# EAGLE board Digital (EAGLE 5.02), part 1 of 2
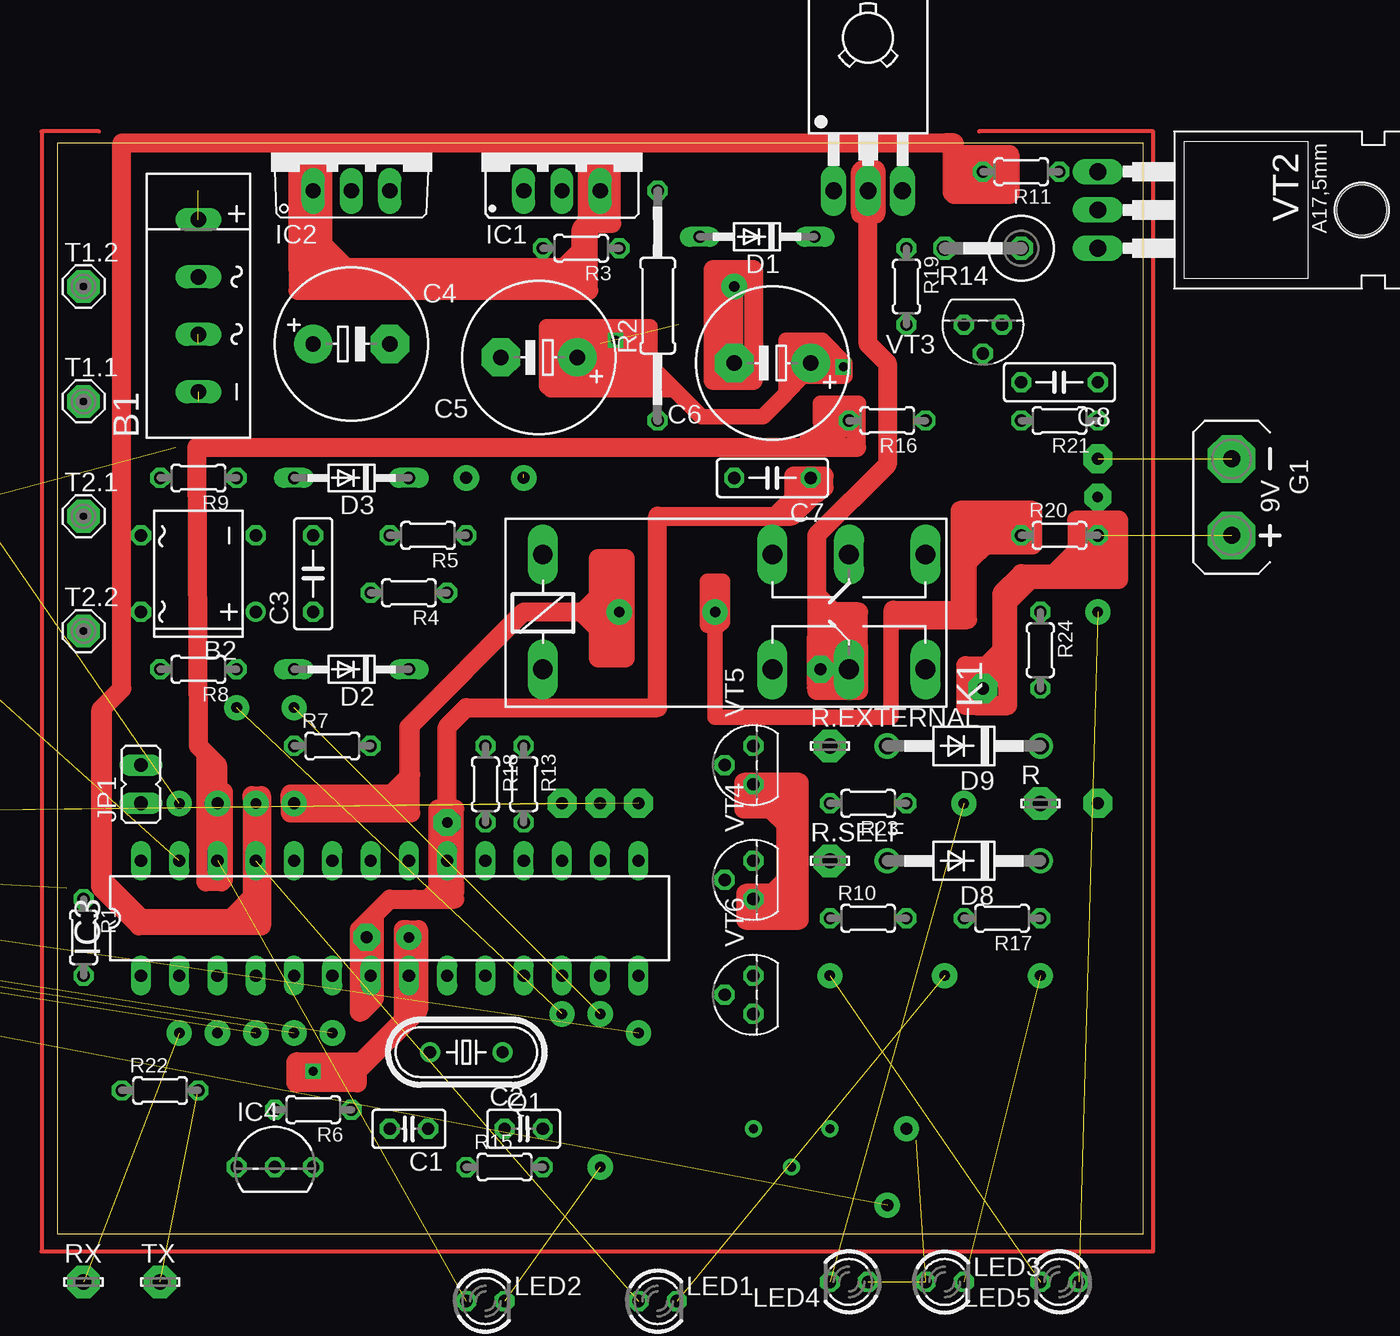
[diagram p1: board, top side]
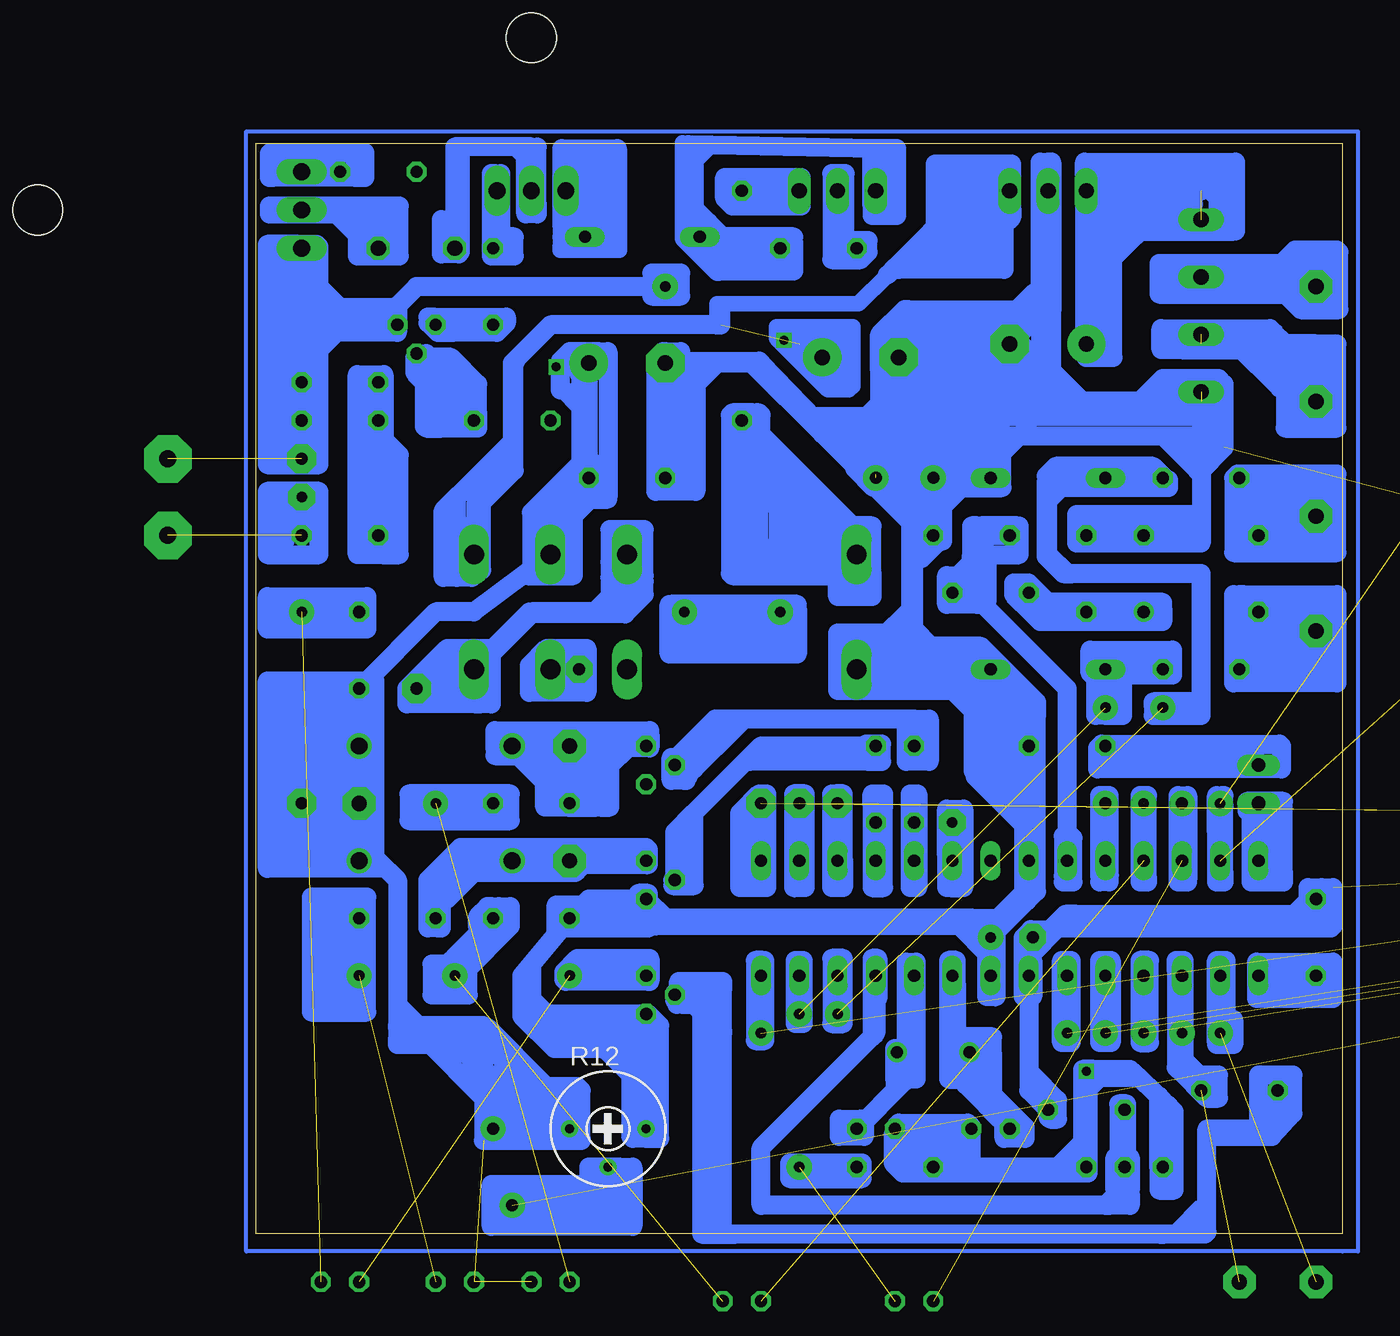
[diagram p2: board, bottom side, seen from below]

Size 72.06 x 72.38 mm. Coordinates in mm from the lower left corner, seen from the top.
Outline: 0,0 72.06,0 72.06,72.38 0,72.38 0,0
Copper layers (1*16): Top 0.035mm / dielectric 1.5mm / Bottom 0.035mm
Design rules "default": minimum track width 10mil, minimum drill 24mil, track to track 8mil, track to pad 8mil, pad to pad 8mil, via to via 8mil, smd to smd 8mil, copper to edge 40mil, drill to drill 8mil, minimum pad ring 10mil, minimum via ring 8mil, stop-mask expansion 4mil, vias tented up to drill 0mil, thermal gap 10mil

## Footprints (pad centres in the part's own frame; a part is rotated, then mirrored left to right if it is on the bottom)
2KBP = drill 1.016 long: + 5.715,0; - -5.715,0; AC1 -1.905,0; AC2 1.905,0
DB = drill 0.813 round: + -2.54,-3.81 | drill 0.813 octagon: - 2.54,-3.81; AC1 2.54,3.81; AC2 -2.54,3.81
C025-025X050 = drill 0.813 octagon: 1 -1.27,0; 2 1.27,0
C050-025X075 = drill 0.813 octagon: 1 -2.54,0; 2 2.54,0
E5-10,5 = drill 1.016 pad 2.54 round: + -2.54,0 | drill 1.016 pad 2.54 octagon: - 2.54,0
DO34-7 = drill 0.813 long: A 3.81,0; C -3.81,0
DO41-10 = drill 1.118 round: A 5.08,0; C -5.08,0
TUXGR_16X2_R2 = drill 1 pad 1.676 round: 1 -32,15.5; 2 -29.46,15.5; 3 -26.92,15.5; 4 -24.38,15.5; 5 -21.84,15.5; 6 -19.3,15.5; 7 -16.76,15.5; 8 -14.22,15.5; 9 -11.68,15.5; 10 -9.14,15.5; 11 -6.6,15.5; 12 -4.06,15.5; 13 -1.52,15.5; 14 1.02,15.5; 15 3.56,15.5; 16 6.1,15.5 | hole 2.5: -37.5,-15.5; 37.5,-15.5; -37.5,15.5; 37.5,15.5
AB9V = drill 1.118 pad 3.15 octagon: + 0,2.54; - 0,-2.54
317TS = drill 1.016 long: 1 -2.54,-2.54; 2 0,-2.54; 3 2.54,-2.54
TO220V = drill 1.016 long: 1 -2.54,-2.54; 2 0,-2.54; 3 2.54,-2.54
DIL28-3 = drill 0.813 long: 1 -16.51,-3.81; 2 -13.97,-3.81; 3 -11.43,-3.81; 4 -8.89,-3.81; 5 -6.35,-3.81; 6 -3.81,-3.81; 7 -1.27,-3.81; 8 1.27,-3.81; 9 3.81,-3.81; 10 6.35,-3.81; 11 8.89,-3.81; 12 11.43,-3.81; 13 13.97,-3.81; 14 16.51,-3.81; 15 16.51,3.81; 16 13.97,3.81; 17 11.43,3.81; 18 8.89,3.81; 19 6.35,3.81; 20 3.81,3.81; 21 1.27,3.81; 22 -1.27,3.81; 23 -3.81,3.81; 24 -6.35,3.81; 25 -8.89,3.81; 26 -11.43,3.81; 27 -13.97,3.81; 28 -16.51,3.81
TO92- = drill 0.813 octagon: 1 -2.54,0; 2 0,0; 3 2.54,0
JP1 = drill 0.914 long: 1 0,-1.27; 2 0,1.27
F4052 = drill 1.321 long: 1 -3.81,3.81; 2 -3.81,-3.81; O1 11.43,-3.81; O2 11.43,3.81; P1 16.51,-3.81; P2 16.51,3.81; S1 21.59,-3.81; S2 21.59,3.81
LED3MM = drill 0.813 octagon: A -1.27,0; K 1.27,0
HC49/S = drill 0.813 round: 1 -2.413,0; 2 2.413,0
LSP10 = drill 1.016 pad 2.159 octagon: MP 0,0
0204/5 = drill 0.813 octagon: 1 -2.54,0; 2 2.54,0
0207/15 = drill 0.813 octagon: 1 -7.62,0; 2 7.62,0
RTRIM3339P = drill 0.61 round: 1 -2.54,0; 2 0,-2.54; 3 2.54,0
0414V = drill 1.016 octagon: 1 -2.54,0; 2 2.54,0
B3F-10XX = drill 1.016 long: 1 -3.251,2.261; 2 3.251,2.261; 3 -3.251,-2.261; 4 3.251,-2.261
MCS10B = drill 1.016 pad 2.159 octagon: MP 0,0
TO126 = drill 1.118 long: 1 -2.286,-5.08; 2 0,-5.08; 3 2.286,-5.08 | hole 3.302: 0,5.08
TO220 = drill 1.118 long: 1 -2.54,-6.35; 2 0,-6.35; 3 2.54,-6.35 | hole 3.302: 0,11.176
TO92 = drill 0.813 octagon: 1 1.27,0; 2 0,1.905; 3 -1.27,0

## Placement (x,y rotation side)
B1  KBP210  [2KBP]  9.36,61.59 90 top
B2  DB107  [DB]  9.36,43.81 90 top
C1  15  [C025-025X050]  23.33,6.98 180 top
C2  15  [C025-025X050]  30.95,6.98 0 top
C3  0.01  [C050-025X075]  16.98,43.81 90 top
C4  470uFx25V  [E5-10,5]  19.52,59.05 0 top
C5  4700u x 16V  [E5-10,5]  31.97,58.16 180 top
C6  [E5-10,5]  47.46,57.78 180 top
C7  0.1u  [C050-025X075]  47.46,50.16 180 top
C8  0.01  [C050-025X075]  66.51,56.51 180 top
D1  1N4004  [DO34-7]  46.44,66.16 180 top
D2  [DO34-7]  19.52,37.46 180 top
D3  [DO34-7]  19.52,50.16 180 top
D4  [DO34-7]  not placed on the board
D5  [DO34-7]  not placed on the board
D6  [DO34-7]  not placed on the board
D7  [DO34-7]  not placed on the board
D8  1N4004  [DO41-10]  60.16,24.76 180 top
D9  1N4004  [DO41-10]  60.16,32.38 180 top
DIS1  [TUXGR_16X2_R2]  not placed on the board
G1  AB5V  [AB9V]  not placed on the board
IC1  LM317  [317TS]  33.49,71.75 0 top
IC2  7805TV  [TO220V]  19.52,71.75 0 top
IC3  MEGA8-P  [DIL28-3]  22.06,20.95 0 top
IC4  DS18B20  [TO92-]  14.44,4.44 0 top
JP1  [JP1]  5.55,29.84 0 top
K1  4052  [F4052]  36.03,41.27 0 top
LED1  [LED3MM]  not placed on the board
LED2  [LED3MM]  not placed on the board
LED3  [LED3MM]  not placed on the board
LED4  [LED3MM]  not placed on the board
LED5  [LED3MM]  not placed on the board
Q1  [HC49/S]  27.14,12.06 180 top
R  LSP10  [LSP10]  65.24,28.57 0 top
R1  10K  [0204/5]  1.74,19.68 270 top
R2  100  [0207/15]  39.84,61.59 90 top
R3  4  [0204/5]  34.76,65.4 180 top
R4  47K  [0204/5]  23.33,42.54 180 top
R5  10K  [0204/5]  24.6,46.35 180 top
R6  4K7  [0204/5]  16.98,8.25 180 top
R7  1K  [0204/5]  18.25,32.38 0 top
R8  10K  [0204/5]  9.36,37.46 180 top
R9  10K  [0204/5]  9.36,50.16 180 top
R10  470  [0204/5]  53.81,20.95 0 top
R11  1K  [0204/5]  63.97,70.48 180 top
R12  22K  [RTRIM3339P]  48.73,6.98 0 bottom
R13  5K6  [0204/5]  30.95,29.84 270 top
R14  15  [0414V]  61.43,65.4 180 top
R15  470  [0204/5]  29.68,4.44 0 top
R16  3K  [0204/5]  55.08,53.97 180 top
R17  470  [0204/5]  62.7,20.95 180 top
R18  5K6  [0204/5]  28.41,29.84 270 top
R19  510  [0204/5]  56.35,62.86 270 top
R20  270K  [0204/5]  66.51,46.35 0 top
R21  150K  [0204/5]  66.51,53.97 180 top
R22  5K6  [0204/5]  6.82,9.52 0 top
R23  470  [0204/5]  53.81,28.57 180 top
R24  33  [0204/5]  65.24,38.73 270 top
R.EXTERNAL  LSP10  [LSP10]  51.27,32.38 0 top
R.SELF  LSP10  [LSP10]  51.27,24.76 0 top
RX  LSP10  [LSP10]  not placed on the board
S1  [B3F-10XX]  not placed on the board
S2  [B3F-10XX]  not placed on the board
S3  [B3F-10XX]  not placed on the board
S4  [B3F-10XX]  not placed on the board
T1.1  T1.1  [MCS10B]  1.74,55.24 0 top
T1.2  MCS10B  [MCS10B]  1.74,62.86 0 top
T2.1  MCS10B  [MCS10B]  1.74,47.62 0 top
T2.2  MCS10B  [MCS10B]  1.74,40 0 top
TX  LSP10  [LSP10]  not placed on the board
VT1  KT973  [TO126]  53.81,74.29 0 top
VT2  KT829  [TO220]  75.4,67.94 270 top
VT3  KT3102  [TO92]  61.43,60.32 180 top
VT4  KT503  [TO92]  46.19,23.49 90 top
VT5  KT503  [TO92]  46.19,31.11 90 top
VT6  KT503  [TO92]  46.19,15.87 90 top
